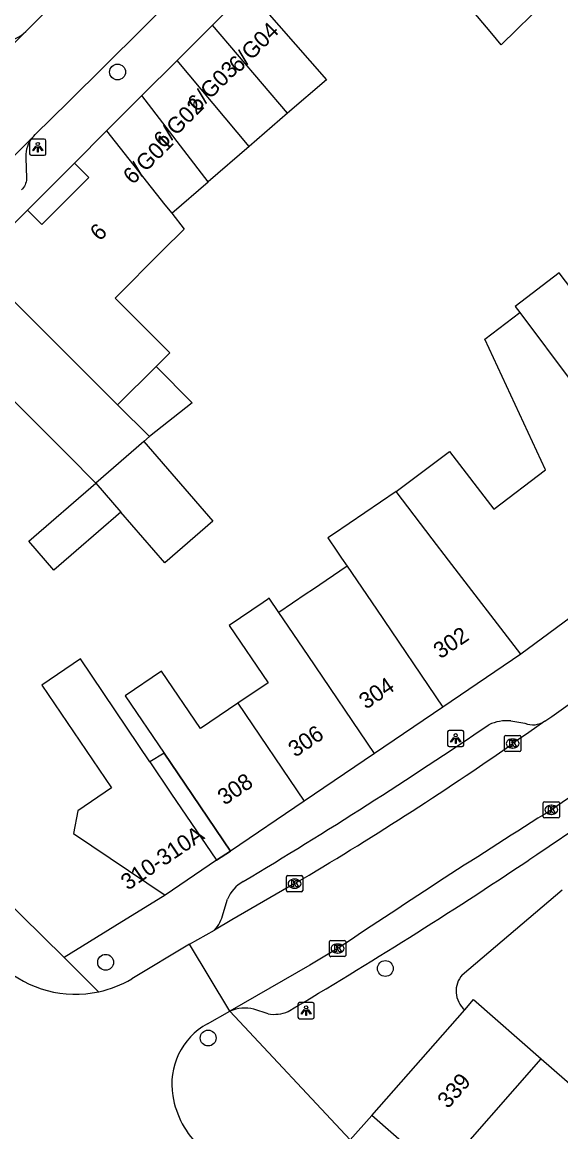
# Model space of a CAD drawing. Extents: x 159222 to 160346, y 381249 to 382166.
# Drawn here: x 160093.8 to 160127.1, y 381674.9 to 381743.4 of the extents above; entities that cross this region are included whole.
import ezdxf

# ---------------------------------------------------------------- set-up
doc = ezdxf.new("R2010")
doc.units = 0
for name, color, linetype in [('IMGEO_Boom', 7, 'Continuous'), ('IMGEO_Kolk', 7, 'Continuous'), ('IMGEO_Lichtpunt', 7, 'Continuous'), ('IMGEO_Muur', 7, 'Continuous'), ('IMGEO_Pand', 7, 'Continuous'), ('IMGEO_Pand_nummerreeks', 7, 'Continuous'), ('IMGEO_Pand_overbouw', 7, 'Continuous'), ('IMGEO_Rijbaan_lokaal_open', 7, 'Continuous'), ('IMGEO_Voetpad_open', 7, 'Continuous')]:
    doc.layers.add(name, color=color, linetype=linetype)

msp = doc.modelspace()

# ---------------------------------------------------------------- linework, layer by layer
at = {"layer": 'IMGEO_Boom'}
for centre in [(160099.696, 381740.327), (160098.957, 381685.385), (160116.224, 381685.004), (160105.287, 381680.709)]:
    msp.add_circle(centre, 0.489, dxfattribs=at)
at = {"layer": 'IMGEO_Kolk'}
for p, q in [((160123.579, 381698.459), (160123.579, 381699.311)), ((160123.654, 381699.385), (160124.506, 381699.385)), ((160124.58, 381699.311), (160124.58, 381698.459)), ((160124.09, 381698.605), (160124.065, 381698.605)), ((160124.067, 381699.165), (160124.092, 381699.165)), ((160124.506, 381698.385), (160123.654, 381698.385)), ((160125.967, 381694.369), (160125.967, 381695.221)), ((160126.042, 381695.295), (160126.894, 381695.295)), ((160126.968, 381695.221), (160126.968, 381694.369)), ((160126.478, 381694.515), (160126.453, 381694.515)), ((160126.455, 381695.075), (160126.48, 381695.075)), ((160126.894, 381694.295), (160126.042, 381694.295)), ((160110.12, 381689.812), (160110.12, 381690.664)), ((160110.195, 381690.738), (160111.047, 381690.738)), ((160110.608, 381690.518), (160110.633, 381690.518)), ((160111.121, 381690.664), (160111.121, 381689.812)), ((160111.047, 381689.738), (160110.195, 381689.738)), ((160110.631, 381689.958), (160110.606, 381689.958)), ((160112.774, 381685.806), (160112.774, 381686.658)), ((160112.849, 381686.732), (160113.701, 381686.732)), ((160113.262, 381686.512), (160113.287, 381686.512)), ((160113.775, 381686.658), (160113.775, 381685.806)), ((160113.701, 381685.732), (160112.849, 381685.732)), ((160113.285, 381685.952), (160113.26, 381685.952))]:
    msp.add_line(p, q, dxfattribs=at)
for points in [[(160123.579, 381698.459), (160123.579, 381699.311)], [(160123.654, 381699.385), (160124.506, 381699.385)], [(160124.58, 381699.311), (160124.58, 381698.459)], [(160123.9, 381699.085), (160124.023, 381699.085), (160124.023, 381698.934), (160124.153, 381699.085), (160124.317, 381699.085), (160124.171, 381698.934), (160124.324, 381698.685), (160124.172, 381698.685), (160124.087, 381698.849), (160124.023, 381698.782), (160124.023, 381698.685), (160123.9, 381698.685), (160123.9, 381699.085)], [(160124.506, 381698.385), (160123.654, 381698.385)], [(160125.967, 381694.369), (160125.967, 381695.221)], [(160126.042, 381695.295), (160126.894, 381695.295)], [(160126.968, 381695.221), (160126.968, 381694.369)], [(160126.288, 381694.995), (160126.411, 381694.995), (160126.411, 381694.844), (160126.541, 381694.995), (160126.705, 381694.995), (160126.559, 381694.844), (160126.712, 381694.595), (160126.56, 381694.595), (160126.475, 381694.759), (160126.411, 381694.692), (160126.411, 381694.595), (160126.288, 381694.595), (160126.288, 381694.995)], [(160126.894, 381694.295), (160126.042, 381694.295)], [(160110.12, 381689.812), (160110.12, 381690.664)], [(160110.195, 381690.738), (160111.047, 381690.738)], [(160110.441, 381690.438), (160110.564, 381690.438), (160110.564, 381690.287), (160110.694, 381690.438), (160110.858, 381690.438), (160110.712, 381690.287), (160110.865, 381690.038), (160110.713, 381690.038), (160110.628, 381690.202), (160110.564, 381690.135), (160110.564, 381690.038), (160110.441, 381690.038), (160110.441, 381690.438)], [(160111.121, 381690.664), (160111.121, 381689.812)], [(160111.047, 381689.738), (160110.195, 381689.738)], [(160112.774, 381685.806), (160112.774, 381686.658)], [(160112.849, 381686.732), (160113.701, 381686.732)], [(160113.095, 381686.432), (160113.218, 381686.432), (160113.218, 381686.281), (160113.348, 381686.432), (160113.512, 381686.432), (160113.366, 381686.281), (160113.519, 381686.032), (160113.367, 381686.032), (160113.282, 381686.196), (160113.218, 381686.129), (160113.218, 381686.032), (160113.095, 381686.032), (160113.095, 381686.432)], [(160113.775, 381686.658), (160113.775, 381685.806)], [(160113.701, 381685.732), (160112.849, 381685.732)]]:
    msp.add_lwpolyline(points, dxfattribs=at)
for centre, start, end in [((160123.656, 381699.309), 91.55205, 178.44795), ((160123.656, 381699.309), 91.55205, 178.44795), ((160124.504, 381699.309), 1.55205, 88.44795), ((160124.504, 381699.309), 1.55205, 88.44795), ((160123.656, 381698.461), 181.55205, 268.44795), ((160123.656, 381698.461), 181.55205, 268.44795), ((160124.504, 381698.461), 271.55205, 358.44795), ((160124.504, 381698.461), 271.55205, 358.44795), ((160126.044, 381695.219), 91.55205, 178.44795), ((160126.044, 381695.219), 91.55205, 178.44795), ((160126.892, 381695.219), 1.55205, 88.44795), ((160126.892, 381695.219), 1.55205, 88.44795), ((160126.044, 381694.371), 181.55205, 268.44795), ((160126.044, 381694.371), 181.55205, 268.44795), ((160126.892, 381694.371), 271.55205, 358.44795), ((160126.892, 381694.371), 271.55205, 358.44795), ((160110.197, 381690.662), 91.55205, 178.44795), ((160110.197, 381690.662), 91.55205, 178.44795), ((160111.045, 381690.662), 1.55205, 88.44795), ((160111.045, 381690.662), 1.55205, 88.44795), ((160110.197, 381689.814), 181.55205, 268.44795), ((160110.197, 381689.814), 181.55205, 268.44795), ((160111.045, 381689.814), 271.55205, 358.44795), ((160111.045, 381689.814), 271.55205, 358.44795), ((160112.851, 381686.656), 91.55205, 178.44795), ((160112.851, 381686.656), 91.55205, 178.44795), ((160113.699, 381686.656), 1.55205, 88.44795), ((160113.699, 381686.656), 1.55205, 88.44795), ((160112.851, 381685.808), 181.55205, 268.44795), ((160112.851, 381685.808), 181.55205, 268.44795), ((160113.699, 381685.808), 271.55205, 358.44795), ((160113.699, 381685.808), 271.55205, 358.44795)]:
    msp.add_arc(centre, 0.0765, start, end, dxfattribs=at)
for centre, major_axis, ratio, start_param, end_param in [((160124.066, 381698.885), (-0.387, 0.002), 0.722429, 4.712389, 7.853982), ((160124.091, 381698.885), (-0.39, 0.002), 0.717154, 1.570796, 4.712389), ((160126.454, 381694.795), (-0.387, 0.002), 0.722429, 4.712389, 7.853982), ((160126.479, 381694.795), (-0.39, 0.002), 0.717154, 1.570796, 4.712389), ((160110.607, 381690.238), (-0.387, 0.002), 0.722429, 4.712389, 7.853982), ((160110.632, 381690.238), (-0.39, 0.002), 0.717154, 1.570796, 4.712389), ((160113.261, 381686.232), (-0.387, 0.002), 0.722429, 4.712389, 7.853982), ((160113.286, 381686.232), (-0.39, 0.002), 0.717154, 1.570796, 4.712389)]:
    msp.add_ellipse(centre, major_axis=major_axis, ratio=ratio, start_param=start_param, end_param=end_param, dxfattribs=at)
at = {"layer": 'IMGEO_Lichtpunt'}
for p, q in [((160094.269, 381736.087), (160094.269, 381735.28)), ((160094.269, 381736.087), (160094.269, 381735.28)), ((160095.171, 381736.182), (160094.363, 381736.182)), ((160095.171, 381736.182), (160094.363, 381736.182)), ((160095.265, 381735.28), (160095.265, 381736.087)), ((160095.265, 381735.28), (160095.265, 381736.087)), ((160094.363, 381735.186), (160095.171, 381735.186)), ((160094.363, 381735.186), (160095.171, 381735.186)), ((160120.067, 381699.598), (160120.067, 381698.791)), ((160120.067, 381699.598), (160120.067, 381698.791)), ((160120.969, 381699.693), (160120.161, 381699.693)), ((160120.969, 381699.693), (160120.161, 381699.693)), ((160121.063, 381698.791), (160121.063, 381699.598)), ((160121.063, 381698.791), (160121.063, 381699.598)), ((160120.161, 381698.697), (160120.969, 381698.697)), ((160120.161, 381698.697), (160120.969, 381698.697)), ((160111.733, 381682.9), (160110.925, 381682.9)), ((160111.733, 381682.9), (160110.925, 381682.9)), ((160110.831, 381682.805), (160110.831, 381681.998)), ((160110.831, 381682.805), (160110.831, 381681.998)), ((160111.827, 381681.998), (160111.827, 381682.805)), ((160111.827, 381681.998), (160111.827, 381682.805)), ((160110.925, 381681.904), (160111.733, 381681.904)), ((160110.925, 381681.904), (160111.733, 381681.904))]:
    msp.add_line(p, q, dxfattribs=at)
for points in [[(160094.643, 381735.751), (160094.682, 381735.723), (160094.494, 381735.461), (160094.456, 381735.488), (160094.643, 381735.751)], [(160094.745, 381735.703), (160094.792, 381735.703), (160094.792, 381735.381), (160094.745, 381735.381), (160094.745, 381735.703)], [(160094.855, 381735.723), (160094.893, 381735.75), (160095.08, 381735.488), (160095.041, 381735.46), (160094.855, 381735.723)], [(160120.441, 381699.262), (160120.48, 381699.234), (160120.292, 381698.972), (160120.254, 381698.999), (160120.441, 381699.262)], [(160120.653, 381699.234), (160120.691, 381699.261), (160120.878, 381698.999), (160120.839, 381698.971), (160120.653, 381699.234)], [(160120.543, 381699.214), (160120.59, 381699.214), (160120.59, 381698.892), (160120.543, 381698.892), (160120.543, 381699.214)], [(160111.205, 381682.469), (160111.244, 381682.441), (160111.056, 381682.179), (160111.018, 381682.206), (160111.205, 381682.469)], [(160111.307, 381682.421), (160111.354, 381682.421), (160111.354, 381682.099), (160111.307, 381682.099), (160111.307, 381682.421)], [(160111.417, 381682.441), (160111.455, 381682.468), (160111.642, 381682.206), (160111.603, 381682.178), (160111.417, 381682.441)]]:
    msp.add_lwpolyline(points, dxfattribs=at)
for centre in [(160094.768, 381735.885), (160120.566, 381699.396), (160111.33, 381682.603)]:
    msp.add_circle(centre, 0.0994, dxfattribs=at)
for centre, start, end in [((160094.363, 381736.087), 90, 180), ((160094.363, 381736.087), 90, 180), ((160095.171, 381736.087), 0, 90), ((160095.171, 381736.087), 0, 90), ((160094.363, 381735.28), 180, 270), ((160094.363, 381735.28), 180, 270), ((160095.171, 381735.28), 270, 0), ((160095.171, 381735.28), 270, 360), ((160120.161, 381699.598), 90, 180), ((160120.161, 381699.598), 90, 180), ((160120.969, 381699.598), 0, 90), ((160120.969, 381699.598), 0, 90), ((160120.161, 381698.791), 180, 270), ((160120.161, 381698.791), 180, 270), ((160120.969, 381698.791), 270, 0), ((160120.969, 381698.791), 270, 360), ((160110.925, 381682.805), 90, 180), ((160110.925, 381682.805), 90, 180), ((160111.733, 381682.805), 0, 90), ((160111.733, 381682.805), 0, 90), ((160110.925, 381681.998), 180, 270), ((160110.925, 381681.998), 180, 270), ((160111.733, 381681.998), 270, 0), ((160111.733, 381681.998), 270, 360)]:
    msp.add_arc(centre, 0.0946, start, end, dxfattribs=at)
at = {"layer": 'IMGEO_Muur'}
for points in [[(160099.526, 381687.617), (160096.39, 381685.677), (160085.816, 381696.065)], [(160102.628, 381689.536), (160099.526, 381687.617)]]:
    msp.add_lwpolyline(points, dxfattribs=at)
at = {"layer": 'IMGEO_Pand'}
for points in [[(160135.024, 381747.857), (160131.851, 381744.721), (160128.478, 381748.136), (160125.648, 381745.339), (160126.197, 381744.785), (160123.374, 381741.995), (160122.79, 381742.695), (160119.588, 381746.535)], [(160105.559, 381743.223), (160107.738, 381745.4)], [(160107.738, 381745.4), (160112.581, 381739.846), (160110.194, 381737.787)], [(160103.38, 381741.046), (160105.559, 381743.223)], [(160110.194, 381737.787), (160105.559, 381743.223)], [(160101.201, 381738.868), (160103.38, 381741.046)], [(160107.808, 381735.728), (160103.38, 381741.046)], [(160099.022, 381736.691), (160101.201, 381738.868)], [(160105.281, 381733.547), (160101.201, 381738.868)], [(160110.194, 381737.787), (160107.808, 381735.728)], [(160097.035, 381734.705), (160099.022, 381736.691)], [(160099.022, 381736.691), (160102.617, 381732.138), (160103.035, 381731.609)], [(160107.808, 381735.728), (160105.281, 381733.547)], [(160097.035, 381734.705), (160097.926, 381733.813), (160095.019, 381730.908), (160094.128, 381731.8)], [(160103.035, 381731.609), (160105.281, 381733.547)], [(160090.888, 381728.562), (160094.128, 381731.8)], [(160103.035, 381731.609), (160103.802, 381730.637), (160102.45, 381729.286), (160099.542, 381726.38), (160102.92, 381722.998), (160102.069, 381722.147)], [(160090.888, 381728.562), (160099.7, 381719.78)], [(160137.421, 381724.939), (160136.388, 381726.195), (160131.256, 381722.282), (160126.951, 381727.928), (160124.231, 381725.854), (160124.515, 381725.478)], [(160116.892, 381714.433), (160120.192, 381716.91), (160122.913, 381713.339), (160126.11, 381715.777), (160122.372, 381723.844), (160124.515, 381725.478)], [(160124.515, 381725.478), (160130.98, 381716.839), (160135.744, 381710.589)], [(160099.7, 381719.78), (160102.069, 381722.147)], [(160102.069, 381722.147), (160104.3, 381719.913), (160101.67, 381717.83)], [(160098.359, 381714.956), (160096.617, 381716.699), (160093.223, 381720.094), (160090.322, 381717.195), (160091.08, 381716.451), (160089.159, 381714.494), (160089.039, 381714.372)], [(160099.7, 381719.78), (160101.67, 381717.83)], [(160101.67, 381717.83), (160101.313, 381717.52)], [(160101.313, 381717.52), (160098.359, 381714.956)], [(160101.313, 381717.52), (160105.575, 381712.612), (160102.604, 381710.034), (160099.899, 381713.171)], [(160099.899, 381713.171), (160095.772, 381709.588), (160094.226, 381711.369), (160098.359, 381714.956)], [(160098.359, 381714.956), (160099.899, 381713.171)], [(160116.892, 381714.433), (160113.023, 381711.81), (160112.742, 381711.62), (160112.679, 381711.577), (160113.23, 381710.765), (160113.524, 381710.332), (160113.866, 381709.828)], [(160124.594, 381704.402), (160120.126, 381710.191), (160119.122, 381711.508), (160116.892, 381714.433)], [(160135.744, 381710.589), (160129.585, 381705.894), (160128.518, 381707.294), (160124.594, 381704.402)], [(160113.866, 381709.828), (160111.722, 381708.375), (160111.345, 381708.119), (160109.648, 381706.969)], [(160113.866, 381709.828), (160115.669, 381707.169), (160119.766, 381701.128)], [(160109.648, 381706.969), (160109.052, 381707.848), (160108.949, 381707.778), (160108.674, 381707.591), (160106.592, 381706.179), (160108.992, 381702.64), (160107.116, 381701.368)], [(160115.549, 381698.268), (160111.452, 381704.309), (160109.648, 381706.969)], [(160102.574, 381698.288), (160101.688, 381697.746), (160097.402, 381704.111), (160095.021, 381702.497), (160099.328, 381696.146), (160097.238, 381694.728), (160096.971, 381693.335), (160102.628, 381689.536)], [(160124.594, 381704.402), (160119.766, 381701.128)], [(160107.116, 381701.368), (160104.812, 381699.805), (160102.411, 381703.345), (160100.173, 381701.828), (160102.574, 381698.288)], [(160107.116, 381701.368), (160111.212, 381695.327)], [(160119.766, 381701.128), (160115.549, 381698.268)], [(160102.574, 381698.288), (160103.864, 381696.386), (160106.671, 381692.247)], [(160115.549, 381698.268), (160111.212, 381695.327)], [(160111.212, 381695.327), (160106.671, 381692.247)], [(160106.671, 381692.247), (160105.798, 381691.686), (160102.628, 381689.536)], [(160121.119, 381682.46), (160121.665, 381683.084), (160125.837, 381679.432)], [(160115.395, 381675.92), (160121.119, 381682.46)], [(160119.569, 381672.267), (160125.837, 381679.432)], [(160125.837, 381679.432), (160129.356, 381676.353), (160132.541, 381679.993), (160135.449, 381677.448)], [(160119.569, 381672.267), (160115.395, 381675.92)]]:
    msp.add_lwpolyline(points, dxfattribs=at)
at = {"layer": 'IMGEO_Pand_overbouw'}
msp.add_lwpolyline([(160101.688, 381697.746), (160102.991, 381695.824), (160105.798, 381691.686), (160106.671, 381692.247), (160103.864, 381696.386), (160102.574, 381698.288)], close=True, dxfattribs=at)
at = {"layer": 'IMGEO_Rijbaan_lokaal_open'}
for points in [[(160094.439, 381736.281), (160094.519, 381736.375), (160094.605, 381736.463), (160096.67, 381738.491), (160105.75, 381747.487), (160108.285, 381750), (160109.2, 381750.907), (160112.218, 381753.899), (160112.744, 381754.421), (160115.459, 381757.113), (160124.093, 381765.676), (160129.502, 381771.04), (160131.72, 381773.24), (160104.723, 381800.425)], [(160098.885, 381747.669), (160094.043, 381742.829)], [(160094.043, 381742.829), (160082.537, 381731.45)], [(160083.435, 381725.337), (160094.439, 381736.281)], [(160126.067, 381700.256), (160126.504, 381700.563), (160129.595, 381702.78), (160135.275, 381707.086), (160141.947, 381712.707), (160145.396, 381715.724), (160146.337, 381716.559)], [(160145.656, 381709.578), (160138.973, 381704.025), (160133.365, 381699.681), (160130.946, 381697.856), (160126.471, 381694.798)], [(160126.067, 381700.256), (160125.075, 381699.567), (160124.08, 381698.883)], [(160110.66, 381690.261), (160106.738, 381688.001), (160105.681, 381687.37)], [(160104.14, 381686.501), (160105.681, 381687.37)], [(160104.14, 381686.501), (160100.566, 381684.364)], [(160106.627, 381682.373), (160104.14, 381686.501)], [(160113.312, 381686.255), (160111.552, 381685.211), (160106.627, 381682.373)], [(160105.236, 381681.594), (160106.627, 381682.373)]]:
    msp.add_lwpolyline(points, dxfattribs=at)
for centre, radius, start, end in [((160004.321, 381870.531), 209.298, 300.53584, 304.90353), ((160436.925, 381202.191), 582.274, 122.220258, 123.764094), ((160097.095, 381690.216), 6.804, 228.22297, 282.16894), ((160097.099, 381690.207), 6.794, 282.15009, 300.68445), ((160107.329, 381677.856), 4.284, 119.24585, 189.52577), ((160108.572, 381678.032), 5.539, 189.19605, 227.29384)]:
    msp.add_arc(centre, radius, start, end, dxfattribs=at)
at = {"layer": 'IMGEO_Voetpad_open'}
for points in [[(160094.439, 381736.281), (160094.343, 381736.152), (160094.259, 381736.016), (160094.188, 381735.872), (160094.13, 381735.722), (160094.085, 381735.568), (160094.054, 381735.411), (160094.038, 381735.251), (160094.036, 381735.091), (160094.039, 381735.022), (160094.081, 381733.772), (160094.079, 381733.723), (160094.068, 381733.63), (160094.049, 381733.539), (160094.022, 381733.449), (160093.987, 381733.363), (160093.945, 381733.279), (160093.895, 381733.2), (160093.838, 381733.126), (160093.775, 381733.057)], [(160094.128, 381731.8), (160097.035, 381734.705)], [(160096.39, 381685.677), (160085.816, 381696.065), (160086.567, 381696.806), (160083.91, 381699.411), (160082.91, 381700.391), (160072.67, 381710.428)], [(160123.971, 381700.285), (160124.834, 381700.133)], [(160134.581, 381698.352), (160128.673, 381694.12), (160125.569, 381692.02), (160125.071, 381691.69)], [(160120.973, 381684.618), (160127.136, 381689.854)], [(160102.628, 381689.536), (160099.526, 381687.617), (160096.39, 381685.677)], [(160106.208, 381688.396), (160106.475, 381689.284)], [(160096.39, 381685.677), (160098.529, 381683.565)], [(160106.627, 381682.373), (160114.056, 381674.431)], [(160108.986, 381682.201), (160108.105, 381682.491)], [(160114.056, 381674.431), (160115.395, 381675.92)]]:
    msp.add_lwpolyline(points, dxfattribs=at)
for centre, radius, start, end in [((160092.632, 381744.27), 2.017, 269.75838, 314.39989), ((159936.723, 381974.382), 331.384, 301.01107, 304.12139), ((160123.752, 381697.556), 2.738, 85.41896, 114.61143), ((160125.327, 381701.428), 1.386, 249.13832, 302.25527), ((159946.935, 381958.315), 320.657, 300.61237, 303.74737), ((160108.576, 381688.362), 2.295, 119.30974, 156.31227), ((160103.869, 381688.949), 2.404, 318.92962, 346.69621), ((160122.101, 381683.61), 1.513, 138.22991, 229.51101), ((160107.548, 381680.156), 2.4, 76.57574, 112.55361), ((160109.35, 381684.428), 2.257, 260.71272, 292.74995)]:
    msp.add_arc(centre, radius, start, end, dxfattribs=at)

# ---------------------------------------------------------------- texts
at = {"layer": 'IMGEO_Pand_nummerreeks'}
for s, rotation, p in [('6/G04', 44.92411, (160107.153, 381740.216)), ('6/G03', 44.92411, (160104.613, 381737.816)), ('6/G02', 44.92411, (160102.517, 381735.563)), ('6/G01', 44.92562, (160100.636, 381733.333)), ('6', 44.98292, (160098.596, 381729.846)), ('302', 34.14256, (160119.622, 381704.075)), ('304', 34.14256, (160115.029, 381700.96)), ('306', 34.14256, (160110.664, 381698)), ('308', 34.14256, (160106.301, 381695.041)), ('310-310A', 34.14828, (160100.331, 381689.79)), ('339', 48.80728, (160120.09, 381676.305))]:
    msp.add_text(s, height=1, rotation=rotation, dxfattribs=at).set_placement(p)

doc.saveas('drawing.dxf')
